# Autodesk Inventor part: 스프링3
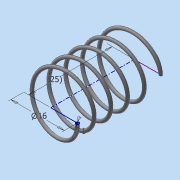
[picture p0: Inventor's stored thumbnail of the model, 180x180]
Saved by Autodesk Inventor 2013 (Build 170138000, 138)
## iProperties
Created: 2015-11
Part Number: 스프링3
Material: 일반
Document SubType Name: Modeling
Designer: dgall
Density: 1 g/cm^3
Author: dgall
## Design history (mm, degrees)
sketch "스케치1"
  geometry: L1 (8, 0)-(0, 0); L2 (0, 0)-(0, 16.67); L3 (0, 16.67)-(8, 16.67); C1 r 0.5 at (8, 0)
  constraints: 6 end point, 1 centre point, 1 coincident, 1 horizontal, 1 parallel, 1 perpendicular, 1 vertical alignment
  dimensions: "d5" = 16 diameter of L1.start L2; "d7" = 16.66987 distance of L1.end L2.end (derived); "d8" = 1 diameter of C1
feature "코일1" pitch "d9" = 10; turns "d11" = 5; dims "d10" = 16.66987 (= d7), "d12" = 0, angle "d13" = 90 deg, angle "d14" = 90 deg, "d15" = 0, "d16" = 0
sketch "스케치2"
  geometry: L1 (-10, 0)-(10, 0); L2 (10, 0)-(10, -5); L3 (10, -5)-(-10, -5); L4 (-10, -5)-(-10, 0); L5 (-10, 30)-(10, 30); L6 (10, 30)-(10, 25); L7 (10, 25)-(-10, 25); L8 (-10, 25)-(-10, 30); 4 further points
  constraints: 16 end point, 4 parallel, 3 midpoint, 2 horizontal, 2 perpendicular, 1 coincident, 1 vertical alignment
  dimensions: "d17" = 25 distance between parallel lines of L7 L1; "d18" = 5 distance of L7.end L5.start; "d19" = 5 distance of L3.end L1.start; "d20" = 20 distance of L2.end L3.end; "d21" = 20 distance of L5.start L5.end
extrude "돌출1" cut sketch "스케치2" stored distance "d22" = 30; taper "d23" = 0 deg
node "솔리드1"
